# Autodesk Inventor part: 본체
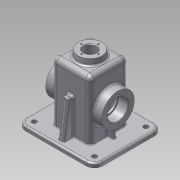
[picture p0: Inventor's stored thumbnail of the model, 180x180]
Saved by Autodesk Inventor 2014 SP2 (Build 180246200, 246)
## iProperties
Created: 2016-08
Part Number: 본체
Material: 알루미늄 6061
Document SubType Name: Modeling
Designer: user
Density: 2.71 g/cm^3
Appearance: 알루미늄 - 평지
Mass: 800.115 g
Surface Area: 912.153 cm^2
Volume: 295.245 cm^3
Author: user
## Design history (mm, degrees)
sketch "스케치1"
  geometry: L1 (-51, -57.5)-(51, -57.5); L2 (65, -43.5)-(65, 43.5); L3 (51, 57.5)-(-51, 57.5); L4 (-65, 43.5)-(-65, -43.5); L5 (-65, -57.5)-(65, 57.5); L6 (65, -57.5)-(-65, 57.5); A1 r 14 centre (-51, 43.5) between (-51, 57.5) and (-65, 43.5); A2 r 14 centre (-51, -43.5) between (-65, -43.5) and (-51, -57.5); A3 r 14 centre (51, -43.5) between (51, -57.5) and (65, -43.5); A4 r 14 centre (51, 43.5) between (65, 43.5) and (51, 57.5); 1 further point
  constraints: 12 end point, 8 point on circle, 8 point on line, 8 tangent, 4 centre point, 3 equal radius, 2 midpoint, 2 parallel, 1 horizontal, 1 perpendicular
  dimensions: "d0" = 130 distance of L6.end L5.end; "d1" = 115 distance of L5.end L6.start; "d4" = 14 radius of A1
extrude "돌출1" new body sketch "스케치1" distance "d2" = 10; taper "d3" = 0 deg
sketch "스케치2"
  geometry: L1 (-51, 0)-(51, 0) reference; L2 (32.5, 0)-(-32.5, 0); L3 (-32.5, 0)-(-32.5, 110); L4 (-32.5, 110)-(32.5, 110); L5 (32.5, 110)-(32.5, 0); 3 further points
  constraints: 8 end point, 2 midpoint, 2 parallel, 1 coincident, 1 horizontal, 1 perpendicular, 1 point on line
  dimensions: "d5" = 65 distance of L3.end L4.end; "d6" = 110 distance of L4.end L2.start
extrude "돌출2" join sketch "스케치2" stored distance "d7" = 65; taper "d8" = 0 deg
sketch "스케치3"
  geometry: L1 (27.5, 27.5)-(-27.5, 27.5); L2 (-27.5, 27.5)-(-27.5, -27.5); L3 (-27.5, -27.5)-(27.5, -27.5); L4 (27.5, -27.5)-(27.5, 27.5); L5 (27.5, 27.5)-(-27.5, -27.5); L6 (-27.5, 27.5)-(27.5, -27.5); 1 further point
  constraints: 12 end point, 2 midpoint, 2 parallel, 1 horizontal, 1 perpendicular
  dimensions: "d9" = 55 distance of L3.end L2.end; "d10" = 55 distance of L2.end L1.end
extrude "돌출3" cut sketch "스케치3" distance "d11" = 105; taper "d12" = 0 deg
sketch "스케치4"
  geometry: L1 (47.5, 55)-(-47.5, 55); L2 (47.5, 55)-(47.5, 82.5); L3 (-47.5, 82.5)-(-47.5, 55); L4 (32.5, 10)-(32.5, 110) reference; L5 (-32.5, 110)-(-32.5, 10) reference; L6 (47.5, 82.5)-(32.5, 82.5); L7 (-32.5, 82.5)-(-47.5, 82.5); L8 (32.5, 82.5)-(32.5, 55); L9 (-32.5, 82.5)-(-32.5, 55); 2 further points
  constraints: 14 end point, 6 point on line, 3 perpendicular, 1 horizontal, 1 midpoint, 1 parallel, 1 vertical alignment
  dimensions: "d13" = 55 distance from line of point (0, 0) L1; "d14" = 95 distance of L1.start L1.end; "d15" = 55 diameter of L6 L1; "d16" = 55 diameter of L7 L1
revolve "회전1" sketch "스케치4" stored, may be unused: angle "d17" = 90 deg
sketch "스케치5"
  geometry: L1 (47.5, 27.5)-(47.5, 82.5) reference; L2 (-47.5, 27.5)-(-47.5, 82.5) reference; L3 (47.5, 55)-(-47.5, 55); L4 (47.5, 55)-(47.5, 72.5); L5 (30.5, 72.2)-(30.5, 70); L6 (30.5, 70)-(27.5, 70); L7 (47.5, 72.5)-(30.8, 72.5); L8 (27.5, 0)-(27.5, 105) reference; L9 (-27.5, 0)-(-27.5, 105) reference; L10 (27.5, 55)-(27.5, 70); L11 (-47.5, 55)-(-47.5, 72.5); L12 (-47.5, 72.5)-(-30.8, 72.5); L13 (-30.5, 72.2)-(-30.5, 70); L14 (-30.5, 70)-(-27.5, 70); L15 (-27.5, 70)-(-27.5, 55); A1 r 0.3 centre (30.8, 72.2) between (30.8, 72.5) and (30.5, 72.2); A2 r 0.3 centre (-30.8, 72.2) between (-30.5, 72.2) and (-30.8, 72.5); 3 further points
  constraints: 22 end point, 12 point on line, 4 perpendicular, 4 point on circle, 4 tangent, 2 centre point, 2 midpoint, 2 parallel, 1 equal radius
  dimensions: "d18" = 17 distance between parallel lines of L5 L1; "d19" = 17 distance between parallel lines of L2 L13; "d20" = 35 diameter of L7 L3; "d21" = 30 diameter of L6 L3; "d22" = 35 diameter of L12 L3; "d23" = 30 diameter of L14 L3; "d146" = 0.3 radius of A1
revolve "회전2" sketch "스케치5" stored, may be unused: angle "d24" = 90 deg
node "작업 평면1"
sketch "스케치6"
  geometry: C1 r 20 at (0, 0); 1 further point
  constraints: 1 centre point, 1 coincident
  dimensions: "d26" = 40 diameter of C1
extrude "돌출4" join sketch "스케치6" stored distance "d27" = 105; taper "d28" = 7 deg
sketch "스케치7"
  geometry: L1 (-49.5, 10)-(-41.068, 70); L2 (-43.5, 10)-(-57.5, 10) reference; L3 (-57.5, 0)-(-57.5, 10) reference; L4 (-32.5, 110)-(-32.5, 10) reference; L5 (-41.068, 70)-(-32.5, 70); 1 further point
  constraints: 4 end point, 2 point on line, 1 perpendicular
  dimensions: "d29" = 8 distance of L1.start L2.end; "d30" = 8 deg angle of L1 L3; "d31" = 70 vertical distance of point (0, 0) L1.end
feature "리브1" sketch "스케치7" dims "d32" = 1, "d33" = 10, "d34" = 0, "d35" = 0, "d36" = 1, "d37" = 1
sketch "스케치8"
  geometry: L1 (57.5, 10)-(43.5, 10) reference; L2 (57.5, 0)-(57.5, 10) reference; L3 (32.5, 10)-(32.5, 110) reference; L4 (49.5, 10)-(41.068, 70); L5 (41.068, 70)-(32.5, 70); 1 further point
  constraints: 4 end point, 2 point on line, 1 perpendicular
  dimensions: "d38" = 70 vertical distance of point (0, 0) L4.end; "d39" = 8 deg angle of L4 L2; "d40" = 8 distance from line of L2 L4.start
feature "리브2" sketch "스케치8" dims "d41" = 1, "d42" = 10, "d43" = 0, "d44" = 0, "d45" = 1, "d46" = 1
sketch "스케치9"
  geometry: L1 (51, 10)-(-51, 10) reference; L2 (-47.5, 27.5)-(-32.5, 27.5) reference; L3 (-42.5, 10)-(-42.5, 27.5); L4 (-27.5, 0)-(-27.5, 105) reference; 1 further point
  constraints: 2 end point, 2 point on line, 1 perpendicular
  dimensions: "d47" = 15 distance between parallel lines of L4 L3
feature "리브3" sketch "스케치9" dims "d48" = 1, "d49" = 6, "d50" = 0, "d51" = 0, "d52" = 1, "d53" = 1
sketch "스케치10"
  geometry: L1 (51, 10)-(-51, 10) reference; L2 (32.5, 27.5)-(47.5, 27.5) reference; L3 (42.5, 10)-(42.5, 27.5); L4 (27.5, 0)-(27.5, 105) reference; 1 further point
  constraints: 2 end point, 2 point on line, 1 perpendicular
  dimensions: "d54" = 15 distance between parallel lines of L3 L4
feature "리브4" sketch "스케치10" dims "d55" = 1, "d56" = 6, "d57" = 0, "d58" = 0, "d59" = 1, "d60" = 1
sketch "스케치11"
  geometry: L1 (-65, -43.5)-(-65, 43.5) reference; L2 (51, -57.5)-(-51, -57.5) reference; L3 (65, 43.5)-(65, -43.5) reference; L4 (-51, 57.5)-(51, 57.5) reference; L5 (27.5, 27.5)-(27.5, -27.5) reference; L6 (27.5, -27.5)-(-27.5, -27.5) reference; L7 (-27.5, -27.5)-(-27.5, 27.5) reference; L8 (-27.5, 27.5)-(27.5, 27.5) reference; L9 (60, 43.5)-(60, -43.5); L10 (51, -52.5)-(-51, -52.5); L11 (-60, -43.5)-(-60, 43.5); L12 (-51, 52.5)-(51, 52.5); A1 r 14 centre (-51, -43.5) between (-65, -43.5) and (-51, -57.5) reference; A2 r 14 centre (51, -43.5) between (51, -57.5) and (65, -43.5) reference; A3 r 14 centre (51, 43.5) between (65, 43.5) and (51, 57.5) reference; A4 r 14 centre (-51, 43.5) between (-51, 57.5) and (-65, 43.5) reference; A5 r 9 centre (51, 43.5) between (60, 43.5) and (51, 52.5); A6 r 9 centre (51, -43.5) between (51, -52.5) and (60, -43.5); A7 r 9 centre (-51, -43.5) between (-60, -43.5) and (-51, -52.5); A8 r 9 centre (-51, 43.5) between (-51, 52.5) and (-60, 43.5); 1 further point
  constraints: 8 end point, 8 point on circle, 4 centre point, 7 other
  dimensions: "d61" = 5 distance between parallel lines of L11 L1
extrude "돌출5" cut sketch "스케치11" distance "d62" = 3; taper "d63" = 0 deg
sketch "스케치12"
  geometry: C1 r 27.5 at (0, 0) reference; A1 r 21 centre (0, 0) between (-21, 0) and (21, 0); 3 further points
  constraints: 4 point on circle, 2 horizontal alignment, 2 vertical alignment, 1 centre point, 1 coincident
  dimensions: "d64" = 42 diameter of A1
hole "구멍1" sketch "스케치12" at (-21, 0), (21, 0), (0, -21), (0, 21) diameter "d65" = 3.242; stored, may be unused: countersink angle "d69" = 90 deg, drill point angle "d71" = 118 deg; dims "d66" = 8, "d67" = 4, "d68" = 2, "d70" = 10
sketch "스케치13"
  geometry: C1 r 27.5 at (0, 0) reference; A1 r 21 centre (0, 0) between (21, 0) and (-21, 0); 3 further points
  constraints: 4 point on circle, 2 horizontal alignment, 2 vertical alignment, 1 centre point, 1 coincident
  dimensions: "d72" = 42 diameter of A1
hole "구멍2" sketch "스케치13" at (21, 0), (-21, 0), (0, 21), (0, -21) diameter "d73" = 3.242; stored, may be unused: countersink angle "d77" = 90 deg, drill point angle "d79" = 118 deg; dims "d74" = 8, "d75" = 4, "d76" = 2, "d78" = 10
sketch "스케치14"
  geometry: A1 r 14.5 centre (0, 0) between (14.5, 0) and (0, 14.5); 3 further points
  constraints: 4 point on circle, 2 horizontal alignment, 2 vertical alignment, 1 centre point, 1 coincident
  dimensions: "d80" = 29 diameter of A1
hole "구멍3" sketch "스케치14" at (14.5, 0), (0, 14.5), (-14.5, 0), (0, -14.5) diameter "d81" = 2.459; stored, may be unused: countersink angle "d85" = 90 deg, drill point angle "d87" = 118 deg; dims "d82" = 7, "d83" = 4, "d84" = 2, "d86" = 9
hole "구멍4" diameter "d90" = 21; stored, may be unused: countersink angle "d94" = 90 deg, drill point angle "d96" = 118 deg; dims "d88" = 10, "d89" = 10, "d91" = 7, "d92" = 4, "d93" = 2, "d95" = 9
hole "구멍5" diameter "d99" = 8; stored, may be unused: countersink angle "d103" = 90 deg, drill point angle "d105" = 118 deg; dims "d97" = 10, "d98" = 10, "d100" = 7, "d101" = 4, "d102" = 2, "d104" = 9
hole "구멍6" diameter "d108" = 8; stored, may be unused: countersink angle "d112" = 90 deg, drill point angle "d114" = 118 deg; dims "d106" = 10, "d107" = 10, "d109" = 7, "d110" = 4, "d111" = 2, "d113" = 9
hole "구멍7" diameter "d117" = 8; stored, may be unused: countersink angle "d121" = 90 deg, drill point angle "d123" = 118 deg; dims "d115" = 10, "d116" = 10, "d118" = 7, "d119" = 4, "d120" = 2, "d122" = 9
hole "구멍8" diameter "d126" = 8; stored, may be unused: countersink angle "d130" = 90 deg, drill point angle "d132" = 118 deg; dims "d124" = 10, "d125" = 10, "d127" = 7, "d128" = 4, "d129" = 2, "d131" = 9
sketch "스케치15"
  geometry: L1 (-100, 65)-(0, 65) reference; L2 (10, 12.5)-(10, 52.5) reference; 2 further points
  constraints: 1 other
  dimensions: "d133" = 32.5 distance from line of L1 point (-16, 32.5); "d134" = 26 distance from line of point (-16, 32.5) L2
feature "엠보싱1" sketch "스케치15" dims "d5" = 65, "d6" = 110, "d135" = 0.5, "d136" = 0
fillet "모깎기1" dims "d137" = 8
fillet "모깎기2" dims "d138" = 8
fillet "모깎기3" dims "d139" = 3
fillet "모깎기4" dims "d140" = 3
fillet "모깎기5" dims "d141" = 3
fillet "모깎기6" dims "d142" = 3
fillet "모깎기7" dims "d143" = 3
fillet "모깎기8" dims "d144" = 3
fillet "모깎기9" dims "d145" = 3
chamfer "모따기1" distance "d147" = 1; stored, may be unused: second distance "d148" = 2, angle "d149" = 45 deg
fillet "모깎기10" dims "d150" = 1
node "솔리드1"
node "투영된 루프1"
